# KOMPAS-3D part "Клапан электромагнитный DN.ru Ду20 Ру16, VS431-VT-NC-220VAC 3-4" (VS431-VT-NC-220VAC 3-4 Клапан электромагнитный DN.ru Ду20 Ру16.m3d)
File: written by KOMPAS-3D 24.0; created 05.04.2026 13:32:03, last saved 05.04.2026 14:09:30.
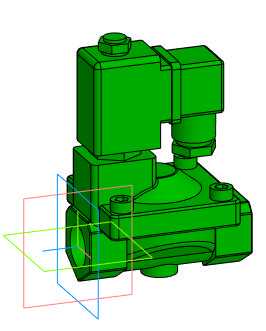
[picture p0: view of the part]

Document properties: Автор: artio; Полное имя файла: C:\Users\artio\OneDrive\Рабочий стол\Клапан электромагнитный DN.ru\VS431\VS431-VT-NC\VS431-VT-NC-220VAC\Ду20\VS431-VT-NC-220VAC 3-4 Клапан электромагнитный DN.ru Ду20 Ру16.m3d

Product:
- Body: Тело 1  | qty 1
    Масса: 1.198355
- Part/product: Клапан электромагнитный DN.ru Ду20 Ру16  | designation VS431-VT-NC-220VAC 3-4
    Масса: 0.907
    Раздел спецификации: Прочие изделия
    Примечание: D130-04713
    additional columns: ef56311e-7521-43dc-8291-0e6108b3d81d; artio; c; Шероховатость не задана; Да

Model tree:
1. Операция без истории:1

Expressions: VS431-VT-NC-220VAC 3-4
